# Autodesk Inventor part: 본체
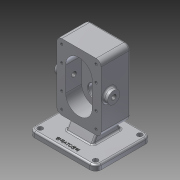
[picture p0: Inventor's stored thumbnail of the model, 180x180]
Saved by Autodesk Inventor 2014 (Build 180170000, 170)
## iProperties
Created: 2020-04
Part Number: 본체
Material: 알루미늄 6061
Document SubType Name: Modeling
Designer: kh
Density: 2.71 g/cm^3
Appearance: 알루미늄 - 평지
Mass: 1476.44 g
Surface Area: 819.925 cm^2
Volume: 544.812 cm^3
Author: kh
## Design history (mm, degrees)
sketch "스케치1"
  geometry: L1 (-50, -60)-(50, -60); L2 (50, -60)-(50, 60); L3 (50, 60)-(-50, 60); L4 (-50, 60)-(-50, -60); L5 (-50, -60)-(50, 60); L6 (50, -60)-(-50, 60); 1 further point
  constraints: 12 end point, 2 midpoint, 2 parallel, 1 horizontal, 1 perpendicular
  dimensions: "d0" = 100 distance of L2.end L3.end; "d1" = 120 distance of L3.end L1.start
extrude "돌출1" new body sketch "스케치1" distance "d2" = 10; taper "d3" = 0 deg
node "작업 평면3"
sketch "스케치2"
  geometry: L1 (20, 150)-(100, 150); L2 (100, 150)-(100, 30); L3 (100, 30)-(20, 30); L4 (20, 30)-(20, 150); L5 (60, 0)-(60, 4.946); L6 (120, 0)-(0, 0) reference
  constraints: 10 end point, 3 parallel, 1 horizontal, 1 perpendicular, 1 other
  dimensions: "d7" = 150 distance between parallel lines of L6 L1; "d8" = 120 distance between parallel lines of L3 L1; "d9" = 80 distance of L1.start L1.end
extrude "돌출2" join sketch "스케치2" distance "d10" = 53; taper "d11" = 0 deg
fillet "모깎기1" dims "d12" = 10
sketch "스케치3"
  geometry: L1 (-60, 112)-(-60, 68); L2 (-84, 112)-(-84, 68); L3 (-36, 68)-(-36, 112); L4 (-110, 0)-(-10, 0) reference; A1 r 24 centre (-60, 112) between (-36, 112) and (-84, 112); A2 r 24 centre (-60, 68) between (-84, 68) and (-36, 68); 3 further points
  constraints: 8 end point, 4 point on circle, 4 tangent, 2 centre point, 2 midpoint, 1 parallel, 1 vertical, 1 vertical alignment
  dimensions: "d13" = 24 radius of A1; "d14" = 90 distance from line of L4 point (-60, 90); "d15" = 44 distance of L1.end L1.start
extrude "돌출3" cut sketch "스케치3" distance "d16" = 29; taper "d17" = 0 deg
hole "구멍2" diameter "d29" = 25; stored, may be unused: countersink angle "d33" = 90 deg, drill point angle "d35" = 0 deg; dims "d27" = 10, "d28" = 10, "d30" = 6, "d31" = 4, "d32" = 2, "d34" = 15
hole "구멍5" diameter "d59" = 25; stored, may be unused: countersink angle "d63" = 90 deg, drill point angle "d65" = 0 deg; dims "d57" = 10, "d58" = 10, "d60" = 6, "d61" = 4, "d62" = 2, "d64" = 15
fillet "모깎기2" dims "d66" = 9
sketch "스케치6"
  geometry: C1 r 12.5 at (60, 112) reference; C2 r 19 at (60, 112); 1 further point
  constraints: 1 centre point, 1 coincident
  dimensions: "d67" = 38 diameter of C2
extrude "돌출4" join sketch "스케치6" distance "d68" = 17; taper "d69" = 0 deg
hole "구멍6" diameter "d72" = 17; stored, may be unused: countersink angle "d76" = 90 deg, drill point angle "d78" = 0 deg; dims "d70" = 10, "d71" = 10, "d73" = 6, "d74" = 4, "d75" = 2, "d77" = 15
hole "구멍7" diameter "d81" = 28; stored, may be unused: countersink angle "d85" = 90 deg, drill point angle "d87" = 0 deg; dims "d79" = 10, "d80" = 10, "d82" = 6, "d83" = 4, "d84" = 2, "d86" = 7.3
chamfer "모따기2" distance "d88" = 0.7; stored, may be unused: second distance "d89" = 2, angle "d90" = 30 deg
sketch "스케치7"
  geometry: L1 (33, 30)-(-20, 30) reference; L2 (40, 10)-(-40, 10) reference; L3 (-20, 10)-(-8.453, 30); L4 (21.453, 30)-(33, 10); L5 (50, 10)-(50, 0) reference; L6 (-8.453, 30)-(21.453, 30); L7 (-20, 10)-(33, 10); 1 further point
  constraints: 8 end point, 4 point on line, 2 collinear
  dimensions: "d91" = 17 distance from line of L5 L4.end; "d92" = 53 distance of L4.end L3.start; "d93" = 60 deg angle of L2 L3; "d94" = 60 deg angle of L2 L4
extrude "돌출5" join sketch "스케치7" stored distance "d95" = 48; taper "d96" = 0 deg
sketch "스케치8"
  geometry: L1 (40, 60)-(-40, 60) reference; L2 (50, -50)-(50, 50) reference; L3 (-40, -60)-(40, -60) reference; L4 (-50, 50)-(-50, -50) reference; A1 r 10 centre (-40, 50) between (-40, 60) and (-50, 50) reference; A2 r 10 centre (40, 50) between (50, 50) and (40, 60) reference; A3 r 10 centre (40, -50) between (40, -60) and (50, -50) reference; A4 r 10 centre (-40, -50) between (-50, -50) and (-40, -60) reference; 1 further point
hole "구멍8" sketch "스케치8" at (-40, 50), (40, 50), (-40, -50), (40, -50) diameter "d97" = 9; stored, may be unused: countersink angle "d101" = 90 deg, drill point angle "d103" = 0 deg; dims "d98" = 6, "d99" = 4, "d100" = 2, "d102" = 7.3
sketch "스케치9"
  geometry: L1 (-84, 68)-(-84, 112) reference; L2 (-36, 112)-(-36, 68) reference; L3 (-100, 141)-(-100, 39) reference; L4 (-91, 30)-(-29, 30) reference; L5 (-20, 39)-(-20, 141) reference; L6 (-29, 150)-(-91, 150) reference; A1 r 24 centre (-60, 68) between (-84, 68) and (-36, 68) reference; A2 r 24 centre (-60, 112) between (-36, 112) and (-84, 112) reference; A3 r 9 centre (-91, 141) between (-91, 150) and (-100, 141) reference; A4 r 9 centre (-91, 39) between (-100, 39) and (-91, 30) reference; A5 r 9 centre (-29, 39) between (-29, 30) and (-20, 39) reference; A6 r 9 centre (-29, 141) between (-20, 141) and (-29, 150) reference; 5 further points
  constraints: 4 vertical alignment
  dimensions: "d104" = 29 distance of point (-29, 112) A6.centre; "d105" = 29 distance of point (-91, 112) A3.centre; "d106" = 44 distance of point (-29, 68) point (-29, 112); "d107" = 44 distance of point (-91, 112) point (-91, 68)
hole "구멍9" sketch "스케치9" at (-91, 112), (-29, 112), (-29, 68), (-91, 68), (-91, 39), (-29, 39), (-29, 141), (-91, 141) diameter "d108" = 4.459; stored, may be unused: countersink angle "d112" = 90 deg, drill point angle "d114" = 118 deg; dims "d109" = 10, "d110" = 4, "d111" = 2, "d113" = 12
sketch "스케치10"
  geometry: L1 (-53, 0)-(-53, 102) reference; L2 (-73, -39)-(7, -39) reference; C1 r 11 at (-38, 51); 1 further point
  constraints: 1 centre point
  dimensions: "d115" = 22 diameter of C1; "d116" = 15 distance from line of L1 C1.centre; "d117" = 90 distance from line of L2 C1.centre
extrude "돌출6" join sketch "스케치10" distance "d118" = 8; taper "d119" = 0 deg
fillet "모깎기4" dims "d121" = 3
hole "구멍10" diameter "d124" = 8.917; stored, may be unused: countersink angle "d128" = 90 deg, drill point angle "d130" = 118 deg; dims "d125" = 10, "d126" = 4, "d127" = 2, "d129" = 12, "d145" = 10, "d146" = 10
sketch "스케치11"
  geometry: L1 (-50, 50)-(-50, -50) reference; L2 (40, 60)-(-40, 60) reference; L3 (-31.634, 25.099)-(-31.634, -25.099); L4 (-31.634, -25.099)-(-48.366, -25.099); L5 (-48.366, -25.099)-(-48.366, 25.099); L6 (-48.366, 25.099)-(-31.634, 25.099); L7 (-48.366, 25.099)-(-31.634, -25.099); L8 (-31.634, 25.099)-(-48.366, -25.099); 3 further points
  constraints: 4 end point, 1 coincident, 1 midpoint, 2 other
  dimensions: "d131" = 10 distance from line of L1 point (-40, 0); "d132" = 60 distance from line of L2 point (-40, 0)
feature "엠보싱1" sketch "스케치11" dims "d0" = 100, "d1" = 120, "d133" = 0.5, "d134" = 0
fillet "모깎기5" dims "d135" = 3
fillet "모깎기6" dims "d136" = 3
fillet "모깎기7" dims "d137" = 3
fillet "모깎기8" dims "d138" = 0.5
chamfer "모따기3" distance "d139" = 1; stored, may be unused: second distance "d140" = 2, angle "d141" = 30 deg
fillet "모깎기9" dims "d142" = 3
fillet "모깎기11" dims "d144" = 3
node "솔리드1"
mirror "대칭1"
node "투영된 루프1"
node "투영된 루프2"
other parameters: "d6" = -17
